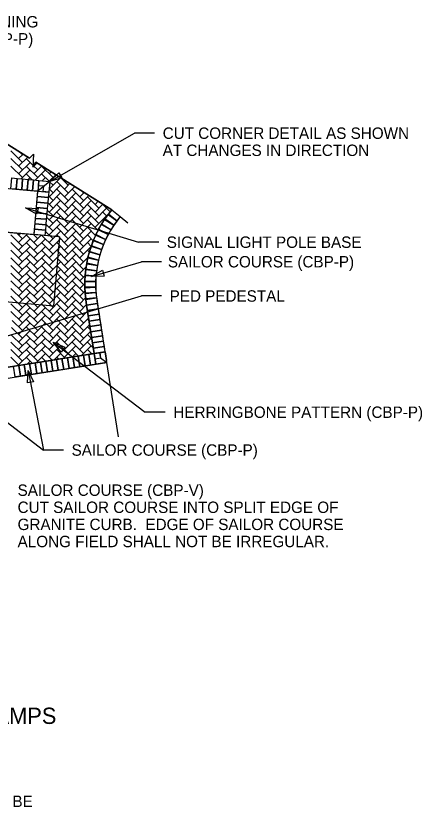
# Model space of a CAD drawing. Extents: x -848 to 1, y -1131 to -115.
# Drawn here: x -753.2 to -703.3, y -866.2 to -768.8 of the extents above; entities that cross this region are included whole.
import ezdxf

# ---------------------------------------------------------------- set-up
doc = ezdxf.new("R2010")
doc.units = 0
for name, color, linetype in [('PV_P_Curb', 7, 'Continuous'), ('PV_P_Curb_Ramp', 7, 'Continuous'), ('PV_P_Joint', 7, 'Continuous'), ('SC_Scratch3', 7, 'Continuous'), ('SH_Text', 7, 'Continuous'), ('TX_X_5', 7, 'Continuous')]:
    doc.layers.add(name, color=color, linetype=linetype)

msp = doc.modelspace()

# ---------------------------------------------------------------- linework, layer by layer
at = {"layer": 'PV_P_Curb'}
msp.add_line((-740.633, -820.473), (-743.269, -803.76), dxfattribs=at)
msp.add_arc((-730.428, -801.735), 13, 140.17518, 188.96168, dxfattribs=at)
at = {"layer": 'PV_P_Curb_Ramp'}
for p, q in [((-755.866, -789.816), (-750.526, -790.292)), ((-751.002, -795.631), (-750.526, -790.292)), ((-747.868, -795.91), (-756.341, -795.155)), ((-747.868, -795.91), (-748.623, -804.383)), ((-757.096, -803.628), (-748.623, -804.383))]:
    msp.add_line(p, q, dxfattribs=at)
at = {"layer": 'PV_P_Joint'}
for p, q in [((-752.433, -786.75), (-753.841, -785.341)), ((-752.433, -787.689), (-753.841, -786.28)), ((-752.902, -786.28), (-752.357, -785.735)), ((-752.902, -787.219), (-751.781, -786.097)), ((-752.433, -785.811), (-752.762, -785.481)), ((-751.14, -787.103), (-751.963, -786.28)), ((-752.433, -788.628), (-753.841, -787.219)), ((-752.902, -788.158), (-751.494, -786.75)), ((-750.555, -788.628), (-751.963, -787.219)), ((-750.555, -787.689), (-751.056, -787.187)), ((-751.024, -787.219), (-750.627, -786.822)), ((-751.024, -788.158), (-750.05, -787.184)), ((-748.677, -788.628), (-750.085, -787.219)), ((-752.579, -788.774), (-751.494, -787.689)), ((-751.227, -788.895), (-751.963, -788.158)), ((-750.855, -788.928), (-749.616, -787.689)), ((-749.165, -789.078), (-750.085, -788.158)), ((-749.146, -788.158), (-748.897, -787.909)), ((-751.717, -788.851), (-751.494, -788.628)), ((-749.084, -789.085), (-750.526, -790.292)), ((-749.992, -789.004), (-749.616, -788.628)), ((-749.146, -790.036), (-747.743, -788.633)), ((-749.13, -789.081), (-748.32, -788.271)), ((-748.677, -789.567), (-749.09, -789.153)), ((-746.798, -790.506), (-748.207, -789.097)), ((-746.798, -789.567), (-747.712, -788.653)), ((-747.268, -789.097), (-747.166, -788.996)), ((-753.196, -790.055), (-753.863, -789.995)), ((-752.528, -790.114), (-753.196, -790.055)), ((-751.861, -790.173), (-752.528, -790.114)), ((-751.194, -790.233), (-751.861, -790.173)), ((-748.677, -790.506), (-749.167, -790.016)), ((-749.146, -790.975), (-747.737, -789.567)), ((-746.798, -791.445), (-748.207, -790.036)), ((-747.268, -790.036), (-746.59, -789.358)), ((-747.268, -790.975), (-746.013, -789.72)), ((-744.92, -791.445), (-746.329, -790.036)), ((-750.526, -790.292), (-751.194, -790.233)), ((-748.677, -791.445), (-749.243, -790.878)), ((-749.146, -791.914), (-747.737, -790.506)), ((-746.798, -792.384), (-748.207, -790.975)), ((-747.268, -791.914), (-745.859, -790.506)), ((-744.92, -792.384), (-746.329, -790.975)), ((-745.39, -790.975), (-744.859, -790.445)), ((-745.39, -791.914), (-744.283, -790.807)), ((-744.92, -790.506), (-745.187, -790.239)), ((-743.042, -792.384), (-744.451, -790.975)), ((-748.677, -792.384), (-749.32, -791.74)), ((-749.146, -792.853), (-747.737, -791.445)), ((-746.798, -793.323), (-748.207, -791.914)), ((-747.268, -792.853), (-745.859, -791.445)), ((-744.92, -793.323), (-746.329, -791.914)), ((-745.39, -792.853), (-743.981, -791.445)), ((-743.042, -793.323), (-744.451, -791.914)), ((-743.512, -791.914), (-743.129, -791.532)), ((-743.512, -792.853), (-742.552, -791.894)), ((-741.658, -792.829), (-742.573, -791.914)), ((-748.677, -793.323), (-749.397, -792.603)), ((-749.146, -793.792), (-747.737, -792.384)), ((-746.798, -794.262), (-748.207, -792.853)), ((-747.268, -793.792), (-745.859, -792.384)), ((-744.92, -794.262), (-746.329, -792.853)), ((-745.39, -793.792), (-743.981, -792.384)), ((-743.042, -794.262), (-744.451, -792.853)), ((-743.512, -793.792), (-742.103, -792.384)), ((-742.062, -793.364), (-742.573, -792.853)), ((-748.677, -794.262), (-749.474, -793.465)), ((-749.146, -794.731), (-747.737, -793.323)), ((-746.798, -795.201), (-748.207, -793.792)), ((-747.268, -794.731), (-745.859, -793.323)), ((-744.92, -795.201), (-746.329, -793.792)), ((-745.39, -794.731), (-743.981, -793.323)), ((-743.139, -795.104), (-744.451, -793.792)), ((-743.512, -794.731), (-742.103, -793.323)), ((-742.444, -793.921), (-742.573, -793.792)), ((-740.417, -793.404), (-739.467, -794.163)), ((-748.677, -795.201), (-749.55, -794.327)), ((-749.146, -795.67), (-747.737, -794.262)), ((-746.798, -796.14), (-748.207, -794.731)), ((-747.268, -795.67), (-745.859, -794.262)), ((-744.92, -796.14), (-746.329, -794.731)), ((-745.39, -795.67), (-743.981, -794.262)), ((-743.448, -795.734), (-744.451, -794.731)), ((-756.341, -795.155), (-751.002, -795.631)), ((-752.433, -797.079), (-753.841, -795.67)), ((-752.433, -796.14), (-753.131, -795.441)), ((-752.902, -795.67), (-752.711, -795.479)), ((-752.902, -796.609), (-751.848, -795.556)), ((-750.555, -797.079), (-751.963, -795.67)), ((-750.555, -796.14), (-751.07, -795.625)), ((-751.024, -795.67), (-750.986, -795.632)), ((-751.024, -796.609), (-750.124, -795.709)), ((-748.677, -797.079), (-750.039, -795.717)), ((-748.677, -796.14), (-749.627, -795.189)), ((-749.146, -796.609), (-747.737, -795.201)), ((-746.798, -797.079), (-748.207, -795.67)), ((-747.268, -796.609), (-745.859, -795.201)), ((-744.92, -797.079), (-746.329, -795.67)), ((-745.39, -796.609), (-743.981, -795.201)), ((-743.732, -796.389), (-744.451, -795.67)), ((-743.512, -795.67), (-743.331, -795.49)), ((-752.433, -798.018), (-753.841, -796.609)), ((-752.902, -797.548), (-751.494, -796.14)), ((-750.555, -798.018), (-751.963, -796.609)), ((-751.024, -797.548), (-749.616, -796.14)), ((-748.677, -798.018), (-750.085, -796.609)), ((-749.146, -797.548), (-747.737, -796.14)), ((-746.798, -798.018), (-748.207, -796.609)), ((-747.268, -797.548), (-745.859, -796.14)), ((-744.92, -798.018), (-746.329, -796.609)), ((-745.39, -797.548), (-743.981, -796.14)), ((-743.987, -797.073), (-744.451, -796.609)), ((-743.98, -797.056), (-743.961, -796.996)), ((-743.723, -796.369), (-743.698, -796.303)), ((-752.433, -798.957), (-753.841, -797.548)), ((-752.902, -798.488), (-751.494, -797.079)), ((-750.555, -798.957), (-751.963, -797.548)), ((-751.024, -798.488), (-749.616, -797.079)), ((-748.677, -798.957), (-750.085, -797.548)), ((-749.146, -798.488), (-747.737, -797.079)), ((-746.798, -798.957), (-748.207, -797.548)), ((-747.268, -798.488), (-745.859, -797.079)), ((-744.92, -798.957), (-746.329, -797.548)), ((-745.39, -798.488), (-743.993, -797.09)), ((-744.214, -797.786), (-744.451, -797.548)), ((-744.205, -797.762), (-744.187, -797.694)), ((-752.433, -799.896), (-753.841, -798.488)), ((-752.902, -799.427), (-751.494, -798.018)), ((-752.902, -800.366), (-751.494, -798.957)), ((-750.555, -799.896), (-751.963, -798.488)), ((-751.024, -799.427), (-749.616, -798.018)), ((-751.024, -800.366), (-749.616, -798.957)), ((-748.677, -799.896), (-750.085, -798.488)), ((-749.146, -799.427), (-747.737, -798.018)), ((-749.146, -800.366), (-747.737, -798.957)), ((-746.798, -799.896), (-748.207, -798.488)), ((-747.268, -799.427), (-745.859, -798.018)), ((-747.268, -800.366), (-745.859, -798.957)), ((-744.92, -799.896), (-746.329, -798.488)), ((-745.39, -799.427), (-744.38, -798.417)), ((-744.405, -798.534), (-744.451, -798.488)), ((-752.433, -800.835), (-753.841, -799.427)), ((-752.902, -801.305), (-751.494, -799.896)), ((-750.555, -800.835), (-751.963, -799.427)), ((-751.024, -801.305), (-749.616, -799.896)), ((-748.677, -800.835), (-750.085, -799.427)), ((-749.146, -801.305), (-747.737, -799.896)), ((-746.798, -800.835), (-748.207, -799.427)), ((-747.268, -801.305), (-745.859, -799.896)), ((-744.92, -800.835), (-746.329, -799.427)), ((-745.39, -800.366), (-744.6, -799.576)), ((-752.433, -801.774), (-753.841, -800.366)), ((-752.902, -802.244), (-751.494, -800.835)), ((-750.555, -801.774), (-751.963, -800.366)), ((-751.024, -802.244), (-749.616, -800.835)), ((-748.677, -801.774), (-750.085, -800.366)), ((-749.146, -802.244), (-747.737, -800.835)), ((-746.798, -801.774), (-748.207, -800.366)), ((-747.268, -802.244), (-745.859, -800.835)), ((-744.92, -801.774), (-746.329, -800.366)), ((-745.39, -801.305), (-744.73, -800.645)), ((-752.433, -802.713), (-753.841, -801.305)), ((-752.902, -803.183), (-751.494, -801.774)), ((-750.555, -802.713), (-751.963, -801.305)), ((-751.024, -803.183), (-749.616, -801.774)), ((-748.677, -802.713), (-750.085, -801.305)), ((-749.146, -803.183), (-747.737, -801.774)), ((-746.798, -802.713), (-748.207, -801.305)), ((-747.268, -803.183), (-745.859, -801.774)), ((-744.92, -802.713), (-746.329, -801.305)), ((-745.39, -802.244), (-744.769, -801.622)), ((-752.433, -803.652), (-753.841, -802.244)), ((-752.902, -804.122), (-751.494, -802.713)), ((-750.555, -803.652), (-751.963, -802.244)), ((-751.024, -804.122), (-749.616, -802.713)), ((-748.677, -803.652), (-750.085, -802.244)), ((-749.146, -804.122), (-747.737, -802.713)), ((-746.798, -803.652), (-748.207, -802.244)), ((-747.268, -804.122), (-745.859, -802.713)), ((-744.92, -803.652), (-746.329, -802.244)), ((-745.39, -803.183), (-744.741, -802.534)), ((-752.433, -804.591), (-753.841, -803.183)), ((-752.902, -805.061), (-751.494, -803.652)), ((-750.555, -804.591), (-751.963, -803.183)), ((-751.024, -805.061), (-749.616, -803.652)), ((-748.677, -804.591), (-750.085, -803.183)), ((-749.146, -805.061), (-747.737, -803.652)), ((-746.798, -804.591), (-748.207, -803.183)), ((-747.268, -805.061), (-745.859, -803.652)), ((-744.92, -804.591), (-746.329, -803.183)), ((-745.39, -804.122), (-744.671, -803.402)), ((-752.433, -805.53), (-753.841, -804.122)), ((-752.902, -806), (-751.494, -804.591)), ((-750.555, -805.53), (-751.963, -804.122)), ((-751.024, -806), (-749.616, -804.591)), ((-748.677, -805.53), (-750.085, -804.122)), ((-749.146, -806), (-747.737, -804.591)), ((-746.798, -805.53), (-748.207, -804.122)), ((-747.268, -806), (-745.859, -804.591)), ((-744.92, -805.53), (-746.329, -804.122)), ((-745.39, -805.061), (-744.552, -804.223)), ((-752.433, -806.469), (-753.841, -805.061)), ((-752.902, -806.939), (-751.494, -805.53)), ((-750.555, -806.469), (-751.963, -805.061)), ((-751.024, -806.939), (-749.616, -805.53)), ((-748.677, -806.469), (-750.085, -805.061)), ((-749.146, -806.939), (-747.737, -805.53)), ((-746.798, -806.469), (-748.207, -805.061)), ((-747.268, -806.939), (-745.859, -805.53)), ((-744.92, -806.469), (-746.329, -805.061)), ((-745.39, -806), (-744.424, -805.034)), ((-744.414, -805.097), (-744.451, -805.061)), ((-752.433, -807.408), (-753.682, -806.159)), ((-752.902, -807.878), (-751.494, -806.469)), ((-750.555, -807.408), (-751.963, -806)), ((-751.024, -807.878), (-749.616, -806.469)), ((-748.677, -807.408), (-750.085, -806)), ((-749.146, -807.878), (-747.737, -806.469)), ((-746.798, -807.408), (-748.207, -806)), ((-747.268, -807.878), (-745.859, -806.469)), ((-744.92, -807.408), (-746.329, -806)), ((-745.39, -806.939), (-744.296, -805.845)), ((-745.39, -807.878), (-744.169, -806.657)), ((-744.239, -806.212), (-744.451, -806)), ((-752.433, -808.347), (-753.759, -807.021)), ((-752.902, -808.817), (-751.494, -807.408)), ((-750.555, -808.347), (-751.963, -806.939)), ((-751.024, -808.817), (-749.616, -807.408)), ((-748.677, -808.347), (-750.085, -806.939)), ((-749.146, -808.817), (-747.737, -807.408)), ((-746.798, -808.347), (-748.207, -806.939)), ((-747.268, -808.817), (-745.859, -807.408)), ((-744.92, -808.347), (-746.329, -806.939)), ((-745.39, -808.817), (-744.041, -807.468)), ((-744.063, -807.327), (-744.451, -806.939)), ((-752.433, -809.286), (-753.841, -807.878)), ((-752.902, -809.756), (-751.494, -808.347)), ((-750.555, -809.286), (-751.963, -807.878)), ((-751.024, -809.756), (-749.616, -808.347)), ((-748.677, -809.286), (-750.085, -807.878)), ((-749.146, -809.756), (-747.737, -808.347)), ((-746.798, -809.286), (-748.207, -807.878)), ((-747.268, -809.756), (-745.859, -808.347)), ((-744.92, -809.286), (-746.329, -807.878)), ((-745.39, -809.756), (-743.981, -808.347)), ((-743.887, -808.442), (-744.451, -807.878)), ((-752.433, -810.226), (-753.841, -808.817)), ((-752.902, -810.695), (-751.494, -809.286)), ((-750.555, -810.226), (-751.963, -808.817)), ((-751.024, -810.695), (-749.616, -809.286)), ((-748.677, -810.226), (-750.085, -808.817)), ((-749.146, -810.695), (-747.737, -809.286)), ((-746.798, -810.226), (-748.207, -808.817)), ((-747.268, -810.695), (-745.859, -809.286)), ((-744.92, -810.226), (-746.329, -808.817)), ((-745.177, -810.482), (-743.981, -809.286)), ((-743.711, -809.557), (-744.451, -808.817)), ((-752.433, -811.165), (-753.841, -809.756)), ((-752.902, -811.634), (-751.494, -810.226)), ((-750.555, -811.165), (-751.963, -809.756)), ((-750.751, -811.361), (-749.616, -810.226)), ((-748.79, -811.052), (-750.085, -809.756)), ((-748.521, -811.009), (-747.737, -810.226)), ((-747.167, -810.796), (-748.207, -809.756)), ((-745.545, -810.54), (-746.329, -809.756)), ((-746.291, -810.658), (-745.859, -810.226)), ((-743.923, -810.284), (-744.451, -809.756)), ((-744.062, -810.306), (-743.981, -810.226)), ((-765.781, -815.077), (-742.074, -811.339)), ((-752.845, -811.691), (-753.841, -810.695)), ((-751.223, -811.435), (-751.963, -810.695)), ((-751.866, -811.537), (-751.494, -811.165)), ((-749.601, -811.179), (-750.085, -810.695)), ((-749.636, -811.185), (-749.616, -811.165)), ((-747.978, -810.924), (-748.207, -810.695)), ((-742.84, -810.781), (-742.084, -811.34))]:
    msp.add_line(p, q, dxfattribs=at)
for points in [[(-751.577, -786.225), (-759.02, -781.55)], [(-751.577, -786.225), (-751.502, -786.156), (-751.064, -785.749), (-751.154, -787.349), (-750.778, -786.727)], [(-741.461, -792.58), (-750.778, -786.727)], [(-749.81, -789.693), (-750.468, -789.635), (-750.408, -788.967), (-749.084, -789.085)], [(-749.084, -789.085), (-749.202, -790.41), (-749.869, -790.351), (-749.81, -789.693)], [(-751.002, -795.631), (-750.943, -794.964), (-750.883, -794.296), (-750.824, -793.629), (-750.764, -792.962), (-750.705, -792.294), (-750.645, -791.627), (-750.586, -790.96), (-750.526, -790.292)], [(-742.342, -793.762), (-742.305, -793.705), (-741.916, -793.159), (-741.875, -793.106)], [(-741.875, -793.106), (-741.876, -793.105), (-741.461, -792.58)], [(-742.703, -794.327), (-742.343, -793.762), (-742.342, -793.762)], [(-743.427, -795.69), (-743.4, -795.627), (-743.101, -795.027), (-743.069, -794.971), (-742.741, -794.386), (-742.703, -794.327)], [(-742.703, -794.327), (-742.703, -794.327)], [(-743.698, -796.303), (-743.429, -795.689), (-743.427, -795.69)], [(-743.961, -796.996), (-743.725, -796.369), (-743.723, -796.369)], [(-744.379, -798.409), (-744.207, -797.761), (-744.205, -797.762)], [(-744.187, -797.694), (-743.982, -797.056), (-743.98, -797.056)], [(-764.012, -813.452), (-743.604, -810.234), (-744.544, -804.277), (-744.648, -803.616), (-744.659, -803.532), (-744.724, -802.826), (-744.769, -802.074), (-744.768, -801.333), (-744.727, -800.589), (-744.645, -799.86), (-744.53, -799.14), (-744.379, -798.409)], [(-742.735, -811.443), (-743.397, -811.548), (-743.604, -810.234), (-742.943, -810.129), (-742.84, -810.781)], [(-742.859, -810.657), (-742.943, -810.129), (-742.281, -810.025), (-742.11, -811.108)], [(-742.084, -811.34), (-743.397, -811.548), (-743.502, -810.886), (-742.84, -810.781)]]:
    msp.add_lwpolyline(points, dxfattribs=at)
for points in [[(-753.863, -789.995), (-753.745, -788.67), (-753.078, -788.73), (-753.196, -790.055)], [(-753.196, -790.055), (-753.078, -788.73), (-752.411, -788.789), (-752.528, -790.114)], [(-752.528, -790.114), (-752.411, -788.789), (-751.743, -788.849), (-751.861, -790.173)], [(-751.861, -790.173), (-751.743, -788.849), (-751.076, -788.908), (-751.194, -790.233)], [(-751.194, -790.233), (-751.076, -788.908), (-750.408, -788.967), (-750.526, -790.292)], [(-750.586, -790.96), (-749.261, -791.078), (-749.32, -791.745), (-750.645, -791.627)], [(-750.526, -790.292), (-749.202, -790.41), (-749.261, -791.078), (-750.586, -790.96)], [(-750.645, -791.627), (-749.32, -791.745), (-749.38, -792.412), (-750.705, -792.294)], [(-750.764, -792.962), (-749.439, -793.08), (-749.499, -793.747), (-750.823, -793.629)], [(-750.705, -792.294), (-749.38, -792.412), (-749.439, -793.08), (-750.764, -792.962)], [(-741.461, -792.58), (-740.417, -793.404), (-740.833, -793.93), (-741.876, -793.105)], [(-750.823, -793.629), (-749.499, -793.747), (-749.558, -794.414), (-750.883, -794.296)], [(-742.343, -793.762), (-741.221, -794.476), (-741.581, -795.041), (-742.703, -794.327)], [(-741.916, -793.159), (-740.833, -793.93), (-741.221, -794.476), (-742.305, -793.705)], [(-750.942, -794.964), (-749.618, -795.082), (-749.677, -795.749), (-751.002, -795.631)], [(-750.883, -794.296), (-749.558, -794.414), (-749.618, -795.082), (-750.942, -794.964)], [(-743.099, -795.028), (-741.91, -795.624), (-742.211, -796.223), (-743.4, -795.627)], [(-742.739, -794.387), (-741.581, -795.041), (-741.91, -795.624), (-743.069, -794.971)], [(-743.429, -795.689), (-742.211, -796.223), (-742.48, -796.837), (-743.698, -796.303)], [(-743.725, -796.369), (-742.48, -796.837), (-742.716, -797.464), (-743.961, -796.996)], [(-744.207, -797.761), (-742.921, -798.102), (-743.093, -798.749), (-744.379, -798.409)], [(-743.982, -797.056), (-742.716, -797.464), (-742.921, -798.102), (-744.187, -797.694)], [(-744.396, -798.483), (-743.093, -798.749), (-743.227, -799.406), (-744.53, -799.14)], [(-744.654, -799.923), (-743.332, -800.068), (-743.405, -800.734), (-744.727, -800.589)], [(-744.541, -799.198), (-743.227, -799.406), (-743.332, -800.068), (-744.645, -799.86)], [(-744.733, -800.664), (-743.405, -800.734), (-743.44, -801.403), (-744.768, -801.333)], [(-744.77, -801.404), (-743.44, -801.403), (-743.439, -802.073), (-744.769, -802.074)], [(-744.766, -802.157), (-743.439, -802.073), (-743.397, -802.741), (-744.724, -802.826)], [(-744.721, -802.865), (-743.397, -802.741), (-743.334, -803.408), (-744.659, -803.532)], [(-744.648, -803.616), (-743.334, -803.408), (-743.23, -804.07), (-744.544, -804.277)], [(-744.544, -804.277), (-743.23, -804.07), (-743.126, -804.732), (-744.439, -804.939)], [(-744.439, -804.939), (-743.126, -804.732), (-743.021, -805.394), (-744.335, -805.601)], [(-744.335, -805.601), (-743.021, -805.394), (-742.917, -806.056), (-744.231, -806.263)], [(-744.231, -806.263), (-742.917, -806.056), (-742.813, -806.718), (-744.126, -806.925)], [(-744.126, -806.925), (-742.813, -806.718), (-742.708, -807.379), (-744.022, -807.587)], [(-744.022, -807.587), (-742.708, -807.379), (-742.604, -808.041), (-743.918, -808.248)], [(-743.918, -808.248), (-742.604, -808.041), (-742.499, -808.703), (-743.813, -808.91)], [(-743.813, -808.91), (-742.499, -808.703), (-742.395, -809.365), (-743.709, -809.572)], [(-743.709, -809.572), (-742.395, -809.365), (-742.291, -810.027), (-743.604, -810.234)], [(-746.706, -812.069), (-746.914, -810.756), (-746.252, -810.651), (-746.045, -811.965)], [(-746.045, -811.965), (-746.252, -810.651), (-745.59, -810.547), (-745.383, -811.861)], [(-745.383, -811.861), (-745.59, -810.547), (-744.928, -810.443), (-744.721, -811.756)], [(-744.721, -811.756), (-744.928, -810.443), (-744.266, -810.338), (-744.059, -811.652)], [(-744.059, -811.652), (-744.266, -810.338), (-743.604, -810.234), (-743.397, -811.548)], [(-752.663, -813.009), (-752.87, -811.695), (-752.208, -811.591), (-752.001, -812.904)], [(-752.001, -812.904), (-752.208, -811.591), (-751.546, -811.486), (-751.339, -812.8)], [(-751.339, -812.8), (-751.546, -811.486), (-750.884, -811.382), (-750.677, -812.696)], [(-750.677, -812.696), (-750.884, -811.382), (-750.223, -811.278), (-750.015, -812.591)], [(-750.015, -812.591), (-750.223, -811.278), (-749.561, -811.173), (-749.354, -812.487)], [(-749.354, -812.487), (-749.561, -811.173), (-748.899, -811.069), (-748.692, -812.383)], [(-748.692, -812.383), (-748.899, -811.069), (-748.237, -810.964), (-748.03, -812.278)], [(-748.03, -812.278), (-748.237, -810.964), (-747.575, -810.86), (-747.368, -812.174)], [(-747.368, -812.174), (-747.575, -810.86), (-746.914, -810.756), (-746.706, -812.069)], [(-753.325, -813.113), (-753.532, -811.799), (-752.87, -811.695), (-752.663, -813.009)], [(-753.325, -813.113), (-753.532, -811.799), (-752.87, -811.695), (-752.663, -813.009)]]:
    msp.add_lwpolyline(points, close=True, dxfattribs=at)
at = {"layer": 'SC_Scratch3'}
for points in [[(-759.02, -781.55), (-751.577, -786.225)], [(-750.778, -786.727), (-741.461, -792.58), (-741.916, -793.159), (-742.305, -793.705), (-742.741, -794.386), (-743.101, -795.027), (-743.4, -795.627), (-743.698, -796.303), (-743.961, -796.996), (-744.187, -797.694), (-744.379, -798.409), (-744.53, -799.14), (-744.645, -799.86), (-744.727, -800.589), (-744.768, -801.333), (-744.769, -802.074), (-744.724, -802.826), (-744.659, -803.532), (-744.648, -803.616), (-744.544, -804.277), (-743.604, -810.234), (-764.012, -813.452)]]:
    msp.add_lwpolyline(points, dxfattribs=at)
at = {"layer": 'TX_X_5'}
for p, q in [((-749.084, -789.085), (-738.662, -783.169)), ((-736.188, -783.169), (-738.662, -783.169)), ((-752.039, -792.356), (-738.162, -796.558)), ((-735.688, -796.558), (-738.162, -796.558)), ((-743.93, -800.789), (-737.809, -798.965)), ((-735.335, -798.965), (-737.809, -798.965)), ((-756.222, -808.652), (-737.809, -803.166)), ((-735.335, -803.166), (-737.809, -803.166)), ((-748.654, -808.839), (-737.351, -817.44)), ((-765.148, -810.453), (-749.858, -822.088)), ((-751.725, -812.306), (-749.858, -822.088)), ((-734.877, -817.44), (-737.351, -817.44)), ((-747.384, -822.088), (-749.858, -822.088))]:
    msp.add_line(p, q, dxfattribs=at)
for points in [[(-747.594, -788.671), (-749.084, -789.085), (-747.964, -788.019)], [(-750.702, -793.131), (-752.039, -792.356), (-750.494, -792.41)], [(-742.386, -800.72), (-743.93, -800.789), (-742.6, -800.001)], [(-747.688, -810.046), (-748.654, -808.839), (-747.234, -809.449)], [(-751.813, -813.849), (-751.725, -812.306), (-751.076, -813.709)]]:
    msp.add_lwpolyline(points, close=True, dxfattribs=at)

# ---------------------------------------------------------------- texts
at = {"layer": 'SH_Text'}
for s, height, p in [('TYPICAL PAVER PATTERN LAYOUT AT CURB RAMPS', 2, (-816.629, -855.73)), ('1. FACE OF GRANITE CURB IS IRREGULAR, SAILOR COURSE SHALL BE', 1.4, (-815.661, -865.934))]:
    msp.add_text(s, height=height, dxfattribs=at).set_placement(p)
at = {"layer": 'TX_X_5'}
for s, p in [('SINGLE RUNNING', (-766.602, -770.178)), ('COURSE (CBP-P)', (-766.602, -772.278)), ('CUT CORNER DETAIL AS SHOWN', (-735.202, -783.869)), ('AT CHANGES IN DIRECTION', (-735.202, -785.969)), ('SIGNAL LIGHT POLE BASE', (-734.701, -797.258)), ('SAILOR COURSE (CBP-P)', (-734.567, -799.657)), ('PED PEDESTAL', (-734.349, -803.866)), ('HERRINGBONE PATTERN (CBP-P)', (-733.891, -818.14)), ('SAILOR COURSE (CBP-P)', (-746.398, -822.788)), ('SAILOR COURSE (CBP-V)', (-753.029, -827.718)), ('CUT SAILOR COURSE INTO SPLIT EDGE OF', (-753.029, -829.818)), ('GRANITE CURB.  EDGE OF SAILOR COURSE', (-753.029, -831.918)), ('ALONG FIELD SHALL NOT BE IRREGULAR.', (-753.029, -834.018))]:
    msp.add_text(s, height=1.4, dxfattribs=at).set_placement(p)

doc.saveas('drawing.dxf')
